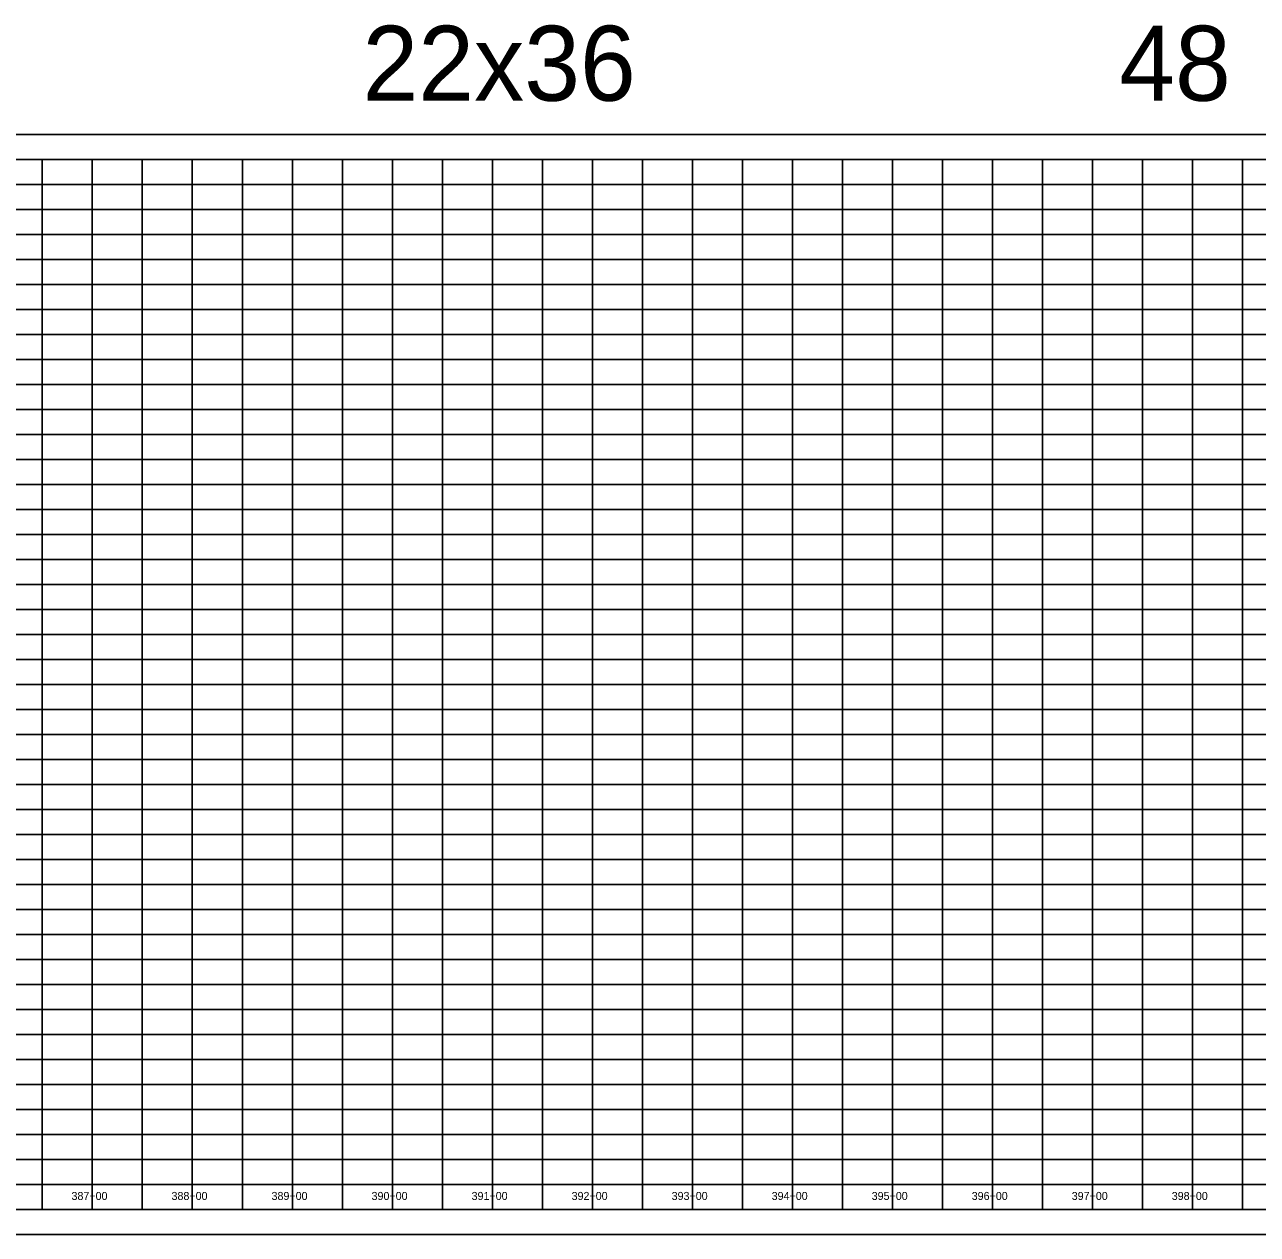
# Model space of a CAD drawing. Extents: x 1873632 to 1926512, y 813126 to 836257.
# Drawn here: x 1916995 to 1918228, y 830505 to 831714 of the extents above; entities that cross this region are included whole.
import ezdxf

# ---------------------------------------------------------------- set-up
doc = ezdxf.new("R2010")
doc.units = 0
for name, color, linetype in [('RD_DDB_StaTX', 7, 'Continuous'), ('RD_PD_WallFill', 7, 'Continuous'), ('RD_SHT_IplotShp', 7, 'Continuous')]:
    doc.layers.add(name, color=color, linetype=linetype)

msp = doc.modelspace()

# ---------------------------------------------------------------- linework, layer by layer
at = {"layer": 'RD_PD_WallFill'}
for p, q in [((1915763, 831579.6), (1921113, 831579.6)), ((1915763, 831579.6), (1917513, 831579.6)), ((1917013, 830529.6), (1917013, 831579.6)), ((1917013, 830529.6), (1917013, 831579.6)), ((1917063, 830529.6), (1917063, 831579.6)), ((1917063, 830529.6), (1917063, 831579.6)), ((1917113, 830529.6), (1917113, 831579.6)), ((1917113, 830529.6), (1917113, 831579.6)), ((1917163, 830529.6), (1917163, 831579.6)), ((1917163, 830529.6), (1917163, 831579.6)), ((1917213, 830529.6), (1917213, 831579.6)), ((1917213, 830529.6), (1917213, 831579.6)), ((1917263, 830529.6), (1917263, 831579.6)), ((1917263, 830529.6), (1917263, 831579.6)), ((1917313, 830529.6), (1917313, 831579.6)), ((1917313, 830529.6), (1917313, 831579.6)), ((1917363, 830529.6), (1917363, 831579.6)), ((1917363, 830529.6), (1917363, 831579.6)), ((1917413, 830529.6), (1917413, 831579.6)), ((1917413, 830529.6), (1917413, 831579.6)), ((1917463, 830529.6), (1917463, 831579.6)), ((1917463, 830529.6), (1917463, 831579.6)), ((1917513, 830529.6), (1917513, 831579.6)), ((1917513, 830529.6), (1917513, 831579.6)), ((1917563, 830529.6), (1917563, 831579.6)), ((1917563, 830529.6), (1917563, 831579.6)), ((1917613, 830529.6), (1917613, 831579.6)), ((1917613, 830529.6), (1917613, 831579.6)), ((1917663, 830529.6), (1917663, 831579.6)), ((1917663, 830529.6), (1917663, 831579.6)), ((1917713, 830529.6), (1917713, 831579.6)), ((1917713, 830529.6), (1917713, 831579.6)), ((1917763, 830529.6), (1917763, 831579.6)), ((1917763, 830529.6), (1917763, 831579.6)), ((1917813, 830529.6), (1917813, 831579.6)), ((1917813, 830529.6), (1917813, 831579.6)), ((1917863, 830529.6), (1917863, 831579.6)), ((1917863, 830529.6), (1917863, 831579.6)), ((1917913, 830529.6), (1917913, 831579.6)), ((1917913, 830529.6), (1917913, 831579.6)), ((1917963, 830529.6), (1917963, 831579.6)), ((1917963, 830529.6), (1917963, 831579.6)), ((1918013, 830529.6), (1918013, 831579.6)), ((1918013, 830529.6), (1918013, 831579.6)), ((1918063, 830529.6), (1918063, 831579.6)), ((1918063, 830529.6), (1918063, 831579.6)), ((1918113, 830529.6), (1918113, 831579.6)), ((1918113, 830529.6), (1918113, 831579.6)), ((1918163, 830529.6), (1918163, 831579.6)), ((1918163, 830529.6), (1918163, 831579.6)), ((1918213, 830529.6), (1918213, 831579.6)), ((1918213, 830529.6), (1918213, 831579.6)), ((1916213, 831554.6), (1921113, 831554.6)), ((1916213, 831554.6), (1921113, 831554.6)), ((1916213, 831529.6), (1921113, 831529.6)), ((1916213, 831504.6), (1921113, 831504.6)), ((1916213, 831479.6), (1921113, 831479.6)), ((1916213, 831454.6), (1921113, 831454.6)), ((1915763, 831429.6), (1921113, 831429.6)), ((1915763, 831404.6), (1921113, 831404.6)), ((1915763, 831379.6), (1921113, 831379.6)), ((1915763, 831354.6), (1921113, 831354.6)), ((1915763, 831329.6), (1921113, 831329.6)), ((1915763, 831304.6), (1921113, 831304.6)), ((1915763, 831279.6), (1921113, 831279.6)), ((1915763, 831254.6), (1921113, 831254.6)), ((1915763, 831229.6), (1921113, 831229.6)), ((1915763, 831204.6), (1921113, 831204.6)), ((1915763, 831179.6), (1921113, 831179.6)), ((1915763, 831154.6), (1921113, 831154.6)), ((1915763, 831129.6), (1921113, 831129.6)), ((1915763, 831104.6), (1921113, 831104.6)), ((1915763, 831079.6), (1921113, 831079.6)), ((1915763, 831054.6), (1921113, 831054.6)), ((1915763, 831029.6), (1921113, 831029.6)), ((1915763, 831004.6), (1921113, 831004.6)), ((1915763, 830979.6), (1921113, 830979.6)), ((1915763, 830954.6), (1921113, 830954.6)), ((1915763, 830929.6), (1921113, 830929.6)), ((1915763, 830904.6), (1921113, 830904.6)), ((1915763, 830879.6), (1921113, 830879.6)), ((1915763, 830854.6), (1921113, 830854.6)), ((1915763, 830829.6), (1921113, 830829.6)), ((1915763, 830804.6), (1921113, 830804.6)), ((1915763, 830779.6), (1921113, 830779.6)), ((1915763, 830754.6), (1921113, 830754.6)), ((1915763, 830729.6), (1921113, 830729.6)), ((1915763, 830704.6), (1921113, 830704.6)), ((1915763, 830679.6), (1921113, 830679.6)), ((1915763, 830654.6), (1921113, 830654.6)), ((1915763, 830629.6), (1921113, 830629.6)), ((1915763, 830604.6), (1921113, 830604.6)), ((1915763, 830579.6), (1921113, 830579.6)), ((1915763, 830554.6), (1921113, 830554.6)), ((1915763, 830529.6), (1921113, 830529.6)), ((1915763, 830529.6), (1921113, 830529.6))]:
    msp.add_line(p, q, dxfattribs=at)
at = {"layer": 'RD_SHT_IplotShp'}
msp.add_lwpolyline([(1915738, 830504.6), (1921138, 830504.6), (1921138, 831604.6), (1915738, 831604.6)], close=True, dxfattribs=at)

# ---------------------------------------------------------------- texts
at = {"layer": 'RD_DDB_StaTX'}
for s, p in [('387+00', (1917042.2, 830539)), ('388+00', (1917142.2, 830539)), ('389+00', (1917242.2, 830539)), ('390+00', (1917342.2, 830539)), ('391+00', (1917442.2, 830539)), ('392+00', (1917542.2, 830539)), ('393+00', (1917642.2, 830539)), ('394+00', (1917742.2, 830539)), ('395+00', (1917842.2, 830539)), ('396+00', (1917942.2, 830539)), ('397+00', (1918042.2, 830539)), ('398+00', (1918142.2, 830539))]:
    msp.add_text(s, height=8, dxfattribs=at).set_placement(p)
at = {"layer": 'RD_PD_WallFill'}
for s, p in [('22x36', (1917333.1, 831638.3)), ('22x36', (1917333.1, 831638.3)), ('48', (1918089.7, 831638.3)), ('48', (1918089.7, 831638.3))]:
    msp.add_text(s, height=75, dxfattribs=at).set_placement(p)

doc.saveas('drawing.dxf')
